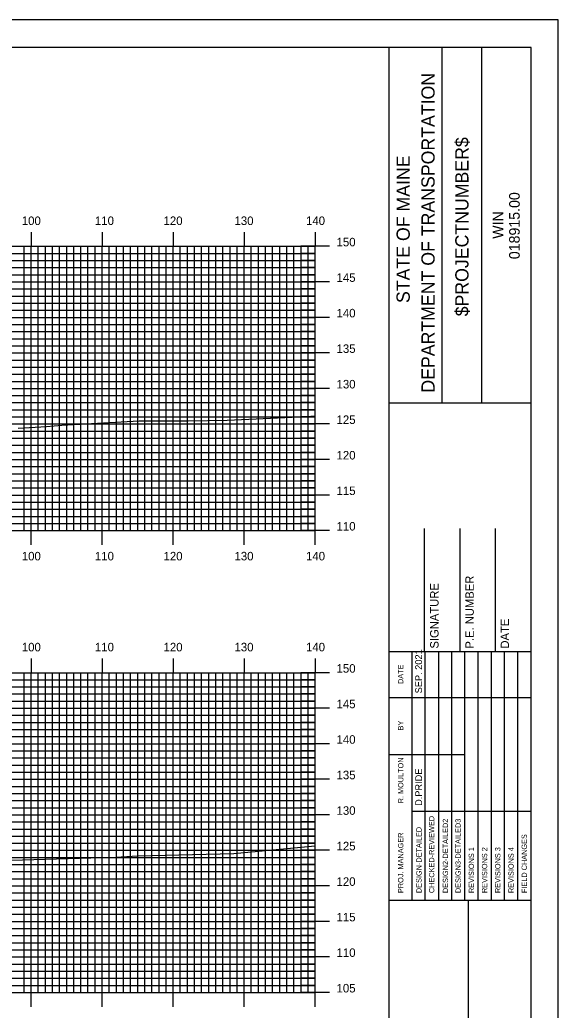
# Model space of a CAD drawing. Extents: x 1790124 to 1790467, y 442591 to 442811.
# Drawn here: x 1790388.1 to 1790463.9, y 442671.2 to 442810.5 of the extents above; entities that cross this region are included whole.
import ezdxf

# ---------------------------------------------------------------- set-up
doc = ezdxf.new("R2010")
doc.units = 0
for name, color, linetype in [('BORDER', 7, 'Continuous'), ('H_V ANNOTATION', 7, 'Continuous'), ('MAJOR', 7, 'Continuous'), ('MINOR', 7, 'Continuous'), ('PLOT BOUNDARY', 7, 'Continuous'), ('S_Roadway_Centerline', 7, 'Continuous')]:
    doc.layers.add(name, color=color, linetype=linetype)

msp = doc.modelspace()

# ---------------------------------------------------------------- linework, layer by layer
at = {"layer": 'BORDER'}
for p, q in [((1790440.1, 442596.67), (1790440.1, 442806.67)), ((1790447.55, 442756.66), (1790447.55, 442806.66)), ((1790453.14, 442756.66), (1790453.14, 442806.66)), ((1790440.1, 442756.65), (1790460.1, 442756.65)), ((1790445.1, 442721.67), (1790445.1, 442738.97)), ((1790450.1, 442721.67), (1790450.1, 442738.97)), ((1790455.1, 442721.67), (1790455.1, 442738.97)), ((1790440.1, 442721.67), (1790460.1, 442721.67)), ((1790440.1, 442686.67), (1790460.1, 442686.67)), ((1790451.28, 442616.67), (1790451.28, 442686.67))]:
    msp.add_line(p, q, dxfattribs=at)
msp.add_lwpolyline([(1790140.1, 442596.67), (1790460.1, 442596.67), (1790460.1, 442806.67), (1790140.1, 442806.67)], close=True, dxfattribs=at)
for points in [[(1790443.33, 442715.17), (1790443.33, 442721.67)], [(1790445.19, 442686.68), (1790445.19, 442721.67)], [(1790447.05, 442721.67), (1790447.05, 442686.68)], [(1790448.92, 442686.68), (1790448.92, 442721.67)], [(1790450.78, 442686.68), (1790450.78, 442721.67)], [(1790452.64, 442686.68), (1790452.64, 442721.67)], [(1790454.51, 442686.68), (1790454.51, 442721.67)], [(1790456.37, 442686.68), (1790456.37, 442721.67)], [(1790458.23, 442686.68), (1790458.23, 442721.67)], [(1790443.33, 442686.68), (1790443.33, 442720.26)], [(1790440.1, 442715.17), (1790460.1, 442715.17)], [(1790440.1, 442707.17), (1790443.33, 442707.17)], [(1790443.33, 442707.17), (1790450.78, 442707.17)], [(1790443.33, 442699.17), (1790460.1, 442699.17)]]:
    msp.add_lwpolyline(points, dxfattribs=at)
at = {"layer": 'MAJOR'}
for p, q in [((1790389.7, 442780.67), (1790389.7, 442778.67)), ((1790399.7, 442780.67), (1790399.7, 442778.67)), ((1790409.7, 442780.67), (1790409.7, 442778.67)), ((1790419.7, 442780.67), (1790419.7, 442778.67)), ((1790429.7, 442780.67), (1790429.7, 442778.67)), ((1790149.7, 442778.67), (1790429.7, 442778.67)), ((1790149.7, 442778.67), (1790429.7, 442778.67)), ((1790389.7, 442738.67), (1790389.7, 442778.67)), ((1790399.7, 442738.67), (1790399.7, 442778.67)), ((1790409.7, 442738.67), (1790409.7, 442778.67)), ((1790419.7, 442738.67), (1790419.7, 442778.67)), ((1790431.7, 442778.67), (1790427.69, 442778.67)), ((1790429.7, 442738.67), (1790429.7, 442778.67)), ((1790429.7, 442738.67), (1790429.7, 442778.67)), ((1790149.7, 442773.67), (1790429.7, 442773.67)), ((1790431.7, 442773.67), (1790427.69, 442773.67)), ((1790149.7, 442768.67), (1790429.7, 442768.67)), ((1790431.7, 442768.67), (1790427.69, 442768.67)), ((1790149.7, 442763.67), (1790429.7, 442763.67)), ((1790431.7, 442763.67), (1790427.69, 442763.67)), ((1790149.7, 442758.67), (1790429.7, 442758.67)), ((1790431.7, 442758.67), (1790427.69, 442758.67)), ((1790149.7, 442753.67), (1790429.7, 442753.67)), ((1790431.7, 442753.67), (1790427.69, 442753.67)), ((1790149.7, 442748.67), (1790429.7, 442748.67)), ((1790431.7, 442748.67), (1790427.69, 442748.67)), ((1790149.7, 442743.67), (1790429.7, 442743.67)), ((1790431.7, 442743.67), (1790427.69, 442743.67)), ((1790149.7, 442738.67), (1790429.7, 442738.67)), ((1790149.7, 442738.67), (1790429.7, 442738.67)), ((1790389.7, 442736.66), (1790389.7, 442738.67)), ((1790399.7, 442736.66), (1790399.7, 442738.67)), ((1790409.7, 442736.66), (1790409.7, 442738.67)), ((1790419.7, 442736.66), (1790419.7, 442738.67)), ((1790431.7, 442738.67), (1790427.69, 442738.67)), ((1790429.7, 442736.66), (1790429.7, 442738.67)), ((1790389.7, 442720.67), (1790389.7, 442718.67)), ((1790399.7, 442720.67), (1790399.7, 442718.67)), ((1790409.7, 442720.67), (1790409.7, 442718.67)), ((1790419.7, 442720.67), (1790419.7, 442718.67)), ((1790429.7, 442720.67), (1790429.7, 442718.67)), ((1790149.7, 442718.67), (1790429.7, 442718.67)), ((1790149.7, 442718.67), (1790429.7, 442718.67)), ((1790389.7, 442673.67), (1790389.7, 442718.67)), ((1790399.7, 442673.67), (1790399.7, 442718.67)), ((1790409.7, 442673.67), (1790409.7, 442718.67)), ((1790419.7, 442673.67), (1790419.7, 442718.67)), ((1790431.7, 442718.67), (1790427.69, 442718.67)), ((1790429.7, 442673.67), (1790429.7, 442718.67)), ((1790429.7, 442673.67), (1790429.7, 442718.67)), ((1790149.7, 442713.67), (1790429.7, 442713.67)), ((1790431.7, 442713.67), (1790427.69, 442713.67)), ((1790149.7, 442708.67), (1790429.7, 442708.67)), ((1790431.7, 442708.67), (1790427.69, 442708.67)), ((1790149.7, 442703.67), (1790429.7, 442703.67)), ((1790431.7, 442703.67), (1790427.69, 442703.67)), ((1790149.7, 442698.67), (1790429.7, 442698.67)), ((1790431.7, 442698.67), (1790427.69, 442698.67)), ((1790149.7, 442693.67), (1790429.7, 442693.67)), ((1790431.7, 442693.67), (1790427.69, 442693.67)), ((1790149.7, 442688.67), (1790429.7, 442688.67)), ((1790431.7, 442688.67), (1790427.69, 442688.67)), ((1790149.7, 442683.67), (1790429.7, 442683.67)), ((1790431.7, 442683.67), (1790427.69, 442683.67)), ((1790149.7, 442678.67), (1790429.7, 442678.67)), ((1790431.7, 442678.67), (1790427.69, 442678.67)), ((1790149.7, 442673.67), (1790429.7, 442673.67)), ((1790149.7, 442673.67), (1790429.7, 442673.67)), ((1790389.7, 442671.66), (1790389.7, 442673.67)), ((1790399.7, 442671.66), (1790399.7, 442673.67)), ((1790409.7, 442671.66), (1790409.7, 442673.67)), ((1790419.7, 442671.66), (1790419.7, 442673.67)), ((1790431.7, 442673.67), (1790427.69, 442673.67)), ((1790429.7, 442671.66), (1790429.7, 442673.67))]:
    msp.add_line(p, q, dxfattribs=at)
at = {"layer": 'MINOR'}
for p, q in [((1790388.7, 442738.67), (1790388.7, 442778.67)), ((1790390.7, 442738.67), (1790390.7, 442778.67)), ((1790391.7, 442738.67), (1790391.7, 442778.67)), ((1790392.7, 442738.67), (1790392.7, 442778.67)), ((1790393.7, 442738.67), (1790393.7, 442778.67)), ((1790394.7, 442738.67), (1790394.7, 442778.67)), ((1790395.7, 442738.67), (1790395.7, 442778.67)), ((1790396.7, 442738.67), (1790396.7, 442778.67)), ((1790397.7, 442738.67), (1790397.7, 442778.67)), ((1790398.7, 442738.67), (1790398.7, 442778.67)), ((1790400.7, 442738.67), (1790400.7, 442778.67)), ((1790401.7, 442738.67), (1790401.7, 442778.67)), ((1790402.7, 442738.67), (1790402.7, 442778.67)), ((1790403.7, 442738.67), (1790403.7, 442778.67)), ((1790404.7, 442738.67), (1790404.7, 442778.67)), ((1790405.7, 442738.67), (1790405.7, 442778.67)), ((1790406.7, 442738.67), (1790406.7, 442778.67)), ((1790407.7, 442738.67), (1790407.7, 442778.67)), ((1790408.7, 442738.67), (1790408.7, 442778.67)), ((1790410.7, 442738.67), (1790410.7, 442778.67)), ((1790411.7, 442738.67), (1790411.7, 442778.67)), ((1790412.7, 442738.67), (1790412.7, 442778.67)), ((1790413.7, 442738.67), (1790413.7, 442778.67)), ((1790414.7, 442738.67), (1790414.7, 442778.67)), ((1790415.7, 442738.67), (1790415.7, 442778.67)), ((1790416.7, 442738.67), (1790416.7, 442778.67)), ((1790417.7, 442738.67), (1790417.7, 442778.67)), ((1790418.7, 442738.67), (1790418.7, 442778.67)), ((1790420.7, 442738.67), (1790420.7, 442778.67)), ((1790421.7, 442738.67), (1790421.7, 442778.67)), ((1790422.7, 442738.67), (1790422.7, 442778.67)), ((1790423.7, 442738.67), (1790423.7, 442778.67)), ((1790424.7, 442738.67), (1790424.7, 442778.67)), ((1790425.7, 442738.67), (1790425.7, 442778.67)), ((1790426.7, 442738.67), (1790426.7, 442778.67)), ((1790427.7, 442738.67), (1790427.7, 442778.67)), ((1790428.7, 442738.67), (1790428.7, 442778.67)), ((1790149.7, 442777.67), (1790429.7, 442777.67)), ((1790429.7, 442777.67), (1790427.69, 442777.67)), ((1790149.7, 442776.67), (1790429.7, 442776.67)), ((1790149.7, 442775.67), (1790429.7, 442775.67)), ((1790429.7, 442776.67), (1790427.69, 442776.67)), ((1790429.7, 442775.67), (1790427.69, 442775.67)), ((1790149.7, 442774.67), (1790429.7, 442774.67)), ((1790429.7, 442774.67), (1790427.69, 442774.67)), ((1790149.7, 442772.67), (1790429.7, 442772.67)), ((1790149.7, 442771.67), (1790429.7, 442771.67)), ((1790429.7, 442772.67), (1790427.69, 442772.67)), ((1790429.7, 442771.67), (1790427.69, 442771.67)), ((1790149.7, 442770.67), (1790429.7, 442770.67)), ((1790429.7, 442770.67), (1790427.69, 442770.67)), ((1790149.7, 442769.67), (1790429.7, 442769.67)), ((1790429.7, 442769.67), (1790427.69, 442769.67)), ((1790149.7, 442767.67), (1790429.7, 442767.67)), ((1790429.7, 442767.67), (1790427.69, 442767.67)), ((1790149.7, 442766.67), (1790429.7, 442766.67)), ((1790429.7, 442766.67), (1790427.69, 442766.67)), ((1790149.7, 442765.67), (1790429.7, 442765.67)), ((1790149.7, 442764.67), (1790429.7, 442764.67)), ((1790429.7, 442765.67), (1790427.69, 442765.67)), ((1790429.7, 442764.67), (1790427.69, 442764.67)), ((1790149.7, 442762.67), (1790429.7, 442762.67)), ((1790149.7, 442761.67), (1790429.7, 442761.67)), ((1790429.7, 442762.67), (1790427.69, 442762.67)), ((1790429.7, 442761.67), (1790427.69, 442761.67)), ((1790149.7, 442760.67), (1790429.7, 442760.67)), ((1790429.7, 442760.67), (1790427.69, 442760.67)), ((1790149.7, 442759.67), (1790429.7, 442759.67)), ((1790429.7, 442759.67), (1790427.69, 442759.67)), ((1790149.7, 442757.67), (1790429.7, 442757.67)), ((1790429.7, 442757.67), (1790427.69, 442757.67)), ((1790149.7, 442756.67), (1790429.7, 442756.67)), ((1790429.7, 442756.67), (1790427.69, 442756.67)), ((1790149.7, 442755.67), (1790429.7, 442755.67)), ((1790149.7, 442754.67), (1790429.7, 442754.67)), ((1790429.7, 442755.67), (1790427.69, 442755.67)), ((1790429.7, 442754.67), (1790427.69, 442754.67)), ((1790149.7, 442752.67), (1790429.7, 442752.67)), ((1790429.7, 442752.67), (1790427.69, 442752.67)), ((1790149.7, 442751.67), (1790429.7, 442751.67)), ((1790149.7, 442750.67), (1790429.7, 442750.67)), ((1790429.7, 442751.67), (1790427.69, 442751.67)), ((1790429.7, 442750.67), (1790427.69, 442750.67)), ((1790149.7, 442749.67), (1790429.7, 442749.67)), ((1790429.7, 442749.67), (1790427.69, 442749.67)), ((1790149.7, 442747.67), (1790429.7, 442747.67)), ((1790429.7, 442747.67), (1790427.69, 442747.67)), ((1790149.7, 442746.67), (1790429.7, 442746.67)), ((1790429.7, 442746.67), (1790427.69, 442746.67)), ((1790149.7, 442745.67), (1790429.7, 442745.67)), ((1790429.7, 442745.67), (1790427.69, 442745.67)), ((1790149.7, 442744.67), (1790429.7, 442744.67)), ((1790429.7, 442744.67), (1790427.69, 442744.67)), ((1790149.7, 442742.67), (1790429.7, 442742.67)), ((1790429.7, 442742.67), (1790427.69, 442742.67)), ((1790149.7, 442741.67), (1790429.7, 442741.67)), ((1790429.7, 442741.67), (1790427.69, 442741.67)), ((1790149.7, 442740.67), (1790429.7, 442740.67)), ((1790149.7, 442739.67), (1790429.7, 442739.67)), ((1790429.7, 442740.67), (1790427.69, 442740.67)), ((1790429.7, 442739.67), (1790427.69, 442739.67)), ((1790388.7, 442673.67), (1790388.7, 442718.67)), ((1790390.7, 442673.67), (1790390.7, 442718.67)), ((1790391.7, 442673.67), (1790391.7, 442718.67)), ((1790392.7, 442673.67), (1790392.7, 442718.67)), ((1790393.7, 442673.67), (1790393.7, 442718.67)), ((1790394.7, 442673.67), (1790394.7, 442718.67)), ((1790395.7, 442673.67), (1790395.7, 442718.67)), ((1790396.7, 442673.67), (1790396.7, 442718.67)), ((1790397.7, 442673.67), (1790397.7, 442718.67)), ((1790398.7, 442673.67), (1790398.7, 442718.67)), ((1790400.7, 442673.67), (1790400.7, 442718.67)), ((1790401.7, 442673.67), (1790401.7, 442718.67)), ((1790402.7, 442673.67), (1790402.7, 442718.67)), ((1790403.7, 442673.67), (1790403.7, 442718.67)), ((1790404.7, 442673.67), (1790404.7, 442718.67)), ((1790405.7, 442673.67), (1790405.7, 442718.67)), ((1790406.7, 442673.67), (1790406.7, 442718.67)), ((1790407.7, 442673.67), (1790407.7, 442718.67)), ((1790408.7, 442673.67), (1790408.7, 442718.67)), ((1790410.7, 442673.67), (1790410.7, 442718.67)), ((1790411.7, 442673.67), (1790411.7, 442718.67)), ((1790412.7, 442673.67), (1790412.7, 442718.67)), ((1790413.7, 442673.67), (1790413.7, 442718.67)), ((1790414.7, 442673.67), (1790414.7, 442718.67)), ((1790415.7, 442673.67), (1790415.7, 442718.67)), ((1790416.7, 442673.67), (1790416.7, 442718.67)), ((1790417.7, 442673.67), (1790417.7, 442718.67)), ((1790418.7, 442673.67), (1790418.7, 442718.67)), ((1790420.7, 442673.67), (1790420.7, 442718.67)), ((1790421.7, 442673.67), (1790421.7, 442718.67)), ((1790422.7, 442673.67), (1790422.7, 442718.67)), ((1790423.7, 442673.67), (1790423.7, 442718.67)), ((1790424.7, 442673.67), (1790424.7, 442718.67)), ((1790425.7, 442673.67), (1790425.7, 442718.67)), ((1790426.7, 442673.67), (1790426.7, 442718.67)), ((1790427.7, 442673.67), (1790427.7, 442718.67)), ((1790428.7, 442673.67), (1790428.7, 442718.67)), ((1790149.7, 442717.67), (1790429.7, 442717.67)), ((1790429.7, 442717.67), (1790427.69, 442717.67)), ((1790149.7, 442716.67), (1790429.7, 442716.67)), ((1790149.7, 442715.67), (1790429.7, 442715.67)), ((1790429.7, 442716.67), (1790427.69, 442716.67)), ((1790429.7, 442715.67), (1790427.69, 442715.67)), ((1790149.7, 442714.67), (1790429.7, 442714.67)), ((1790429.7, 442714.67), (1790427.69, 442714.67)), ((1790149.7, 442712.67), (1790429.7, 442712.67)), ((1790149.7, 442711.67), (1790429.7, 442711.67)), ((1790429.7, 442712.67), (1790427.69, 442712.67)), ((1790429.7, 442711.67), (1790427.69, 442711.67)), ((1790149.7, 442710.67), (1790429.7, 442710.67)), ((1790429.7, 442710.67), (1790427.69, 442710.67)), ((1790149.7, 442709.67), (1790429.7, 442709.67)), ((1790429.7, 442709.67), (1790427.69, 442709.67)), ((1790149.7, 442707.67), (1790429.7, 442707.67)), ((1790429.7, 442707.67), (1790427.69, 442707.67)), ((1790149.7, 442706.67), (1790429.7, 442706.67)), ((1790429.7, 442706.67), (1790427.69, 442706.67)), ((1790149.7, 442705.67), (1790429.7, 442705.67)), ((1790149.7, 442704.67), (1790429.7, 442704.67)), ((1790429.7, 442705.67), (1790427.69, 442705.67)), ((1790429.7, 442704.67), (1790427.69, 442704.67)), ((1790149.7, 442702.67), (1790429.7, 442702.67)), ((1790149.7, 442701.67), (1790429.7, 442701.67)), ((1790429.7, 442702.67), (1790427.69, 442702.67)), ((1790429.7, 442701.67), (1790427.69, 442701.67)), ((1790149.7, 442700.67), (1790429.7, 442700.67)), ((1790429.7, 442700.67), (1790427.69, 442700.67)), ((1790149.7, 442699.67), (1790429.7, 442699.67)), ((1790429.7, 442699.67), (1790427.69, 442699.67)), ((1790149.7, 442697.67), (1790429.7, 442697.67)), ((1790429.7, 442697.67), (1790427.69, 442697.67)), ((1790149.7, 442696.67), (1790429.7, 442696.67)), ((1790429.7, 442696.67), (1790427.69, 442696.67)), ((1790149.7, 442695.67), (1790429.7, 442695.67)), ((1790429.7, 442695.67), (1790427.69, 442695.67)), ((1790149.7, 442694.67), (1790429.7, 442694.67)), ((1790429.7, 442694.67), (1790427.69, 442694.67)), ((1790149.7, 442692.67), (1790429.7, 442692.67)), ((1790429.7, 442692.67), (1790427.69, 442692.67)), ((1790149.7, 442691.67), (1790429.7, 442691.67)), ((1790149.7, 442690.67), (1790429.7, 442690.67)), ((1790429.7, 442691.67), (1790427.69, 442691.67)), ((1790429.7, 442690.67), (1790427.69, 442690.67)), ((1790149.7, 442689.67), (1790429.7, 442689.67)), ((1790429.7, 442689.67), (1790427.69, 442689.67)), ((1790149.7, 442687.67), (1790429.7, 442687.67)), ((1790149.7, 442686.67), (1790429.7, 442686.67)), ((1790429.7, 442687.67), (1790427.69, 442687.67)), ((1790429.7, 442686.67), (1790427.69, 442686.67)), ((1790149.7, 442685.67), (1790429.7, 442685.67)), ((1790429.7, 442685.67), (1790427.69, 442685.67)), ((1790149.7, 442684.67), (1790429.7, 442684.67)), ((1790429.7, 442684.67), (1790427.69, 442684.67)), ((1790149.7, 442682.67), (1790429.7, 442682.67)), ((1790429.7, 442682.67), (1790427.69, 442682.67)), ((1790149.7, 442681.67), (1790429.7, 442681.67)), ((1790429.7, 442681.67), (1790427.69, 442681.67)), ((1790149.7, 442680.67), (1790429.7, 442680.67)), ((1790149.7, 442679.67), (1790429.7, 442679.67)), ((1790429.7, 442680.67), (1790427.69, 442680.67)), ((1790429.7, 442679.67), (1790427.69, 442679.67)), ((1790149.7, 442677.67), (1790429.7, 442677.67)), ((1790149.7, 442676.67), (1790429.7, 442676.67)), ((1790429.7, 442677.67), (1790427.69, 442677.67)), ((1790429.7, 442676.67), (1790427.69, 442676.67)), ((1790149.7, 442675.67), (1790429.7, 442675.67)), ((1790429.7, 442675.67), (1790427.69, 442675.67)), ((1790149.7, 442674.67), (1790429.7, 442674.67)), ((1790429.7, 442674.67), (1790427.69, 442674.67))]:
    msp.add_line(p, q, dxfattribs=at)
at = {"layer": 'PLOT BOUNDARY'}
msp.add_lwpolyline([(1790123.91, 442590.55), (1790463.91, 442590.55), (1790463.91, 442810.55), (1790123.91, 442810.55)], close=True, dxfattribs=at)
at = {"layer": 'S_Roadway_Centerline'}
for points in [[(1790387.89, 442753.06), (1790391.85, 442753.33), (1790394.01, 442753.49), (1790404.92, 442754.13), (1790411.81, 442754.13), (1790417.31, 442754.22), (1790428.48, 442754.74), (1790429.7, 442754.81)], [(1790311.14, 442689.29), (1790316.74, 442690.36), (1790320.96, 442691.1), (1790322, 442691.1), (1790322.96, 442691.25), (1790323.85, 442691.32), (1790329.11, 442691.5), (1790331.43, 442691.36), (1790335.35, 442691.18), (1790344.98, 442691.22), (1790346.53, 442691.46), (1790347.03, 442691.47), (1790361.95, 442691.86), (1790363.08, 442691.88), (1790364.1, 442691.93), (1790375.22, 442692.11), (1790382, 442692.13), (1790398.11, 442692.63), (1790401.63, 442692.71), (1790404.68, 442692.9), (1790418.24, 442693.21), (1790429.7, 442694.28)]]:
    msp.add_lwpolyline(points, dxfattribs=at)

# ---------------------------------------------------------------- texts
at = {"layer": 'BORDER'}
for s, height, p in [('DEPARTMENT OF TRANSPORTATION', 1.8635, (1790446.51, 442758.08)), ('$PROJECTNUMBER$', 1.8635, (1790451.28, 442768.82)), ('STATE OF MAINE', 1.8635, (1790443.01, 442770.69)), ('018915.00', 1.491, (1790458.49, 442776.86)), ('WIN', 1.491, (1790456.17, 442779.73)), ('SIGNATURE', 1.181, (1790447.06, 442722.06)), ('P.E. NUMBER', 1.1811, (1790452.02, 442722.06)), ('DATE', 1.181, (1790456.98, 442722.06)), ('SEP. 2021', 0.969, (1790444.74, 442715.76)), ('DATE', 0.743, (1790442.1, 442717.08)), ('BY', 0.743, (1790442.1, 442710.54)), ('R. MOULTON', 0.745, (1790442.11, 442700.28)), ('D.PRIDE', 0.969, (1790444.74, 442699.92)), ('CHECKED-REVIEWED', 0.7455, (1790446.46, 442687.65)), ('DESIGN2-DETAILED2', 0.7455, (1790448.4, 442687.65)), ('DESIGN3-DETAILED3', 0.7455, (1790450.18, 442687.65)), ('DESIGN-DETAILED', 0.7455, (1790444.67, 442687.65)), ('PROJ. MANAGER', 0.7455, (1790442.1, 442687.65)), ('FIELD CHANGES', 0.7455, (1790459.5, 442687.65)), ('REVISIONS 1', 0.7455, (1790452.05, 442687.65)), ('REVISIONS 2', 0.7455, (1790453.91, 442687.65)), ('REVISIONS 3', 0.7455, (1790455.77, 442687.65)), ('REVISIONS 4', 0.7455, (1790457.64, 442687.65))]:
    msp.add_text(s, height=height, rotation=90, dxfattribs=at).set_placement(p)
at = {"layer": 'H_V ANNOTATION'}
for s, p in [('100', (1790388.38, 442781.67)), ('110', (1790398.68, 442781.67)), ('120', (1790408.34, 442781.67)), ('130', (1790418.33, 442781.67)), ('140', (1790428.4, 442781.67)), ('150', (1790432.7, 442778.67)), ('145', (1790432.7, 442773.67)), ('140', (1790432.7, 442768.67)), ('135', (1790432.7, 442763.67)), ('130', (1790432.7, 442758.67)), ('125', (1790432.7, 442753.67)), ('120', (1790432.7, 442748.67)), ('115', (1790432.7, 442743.67)), ('110', (1790432.7, 442738.67)), ('100', (1790388.38, 442734.47)), ('110', (1790398.68, 442734.47)), ('120', (1790408.34, 442734.47)), ('130', (1790418.33, 442734.47)), ('140', (1790428.4, 442734.47)), ('100', (1790388.38, 442721.67)), ('110', (1790398.68, 442721.67)), ('120', (1790408.34, 442721.67)), ('130', (1790418.33, 442721.67)), ('140', (1790428.4, 442721.67)), ('150', (1790432.7, 442718.67)), ('145', (1790432.7, 442713.67)), ('140', (1790432.7, 442708.67)), ('135', (1790432.7, 442703.67)), ('130', (1790432.7, 442698.67)), ('125', (1790432.7, 442693.67)), ('120', (1790432.7, 442688.67)), ('115', (1790432.7, 442683.67)), ('110', (1790432.7, 442678.67)), ('105', (1790432.7, 442673.67))]:
    msp.add_text(s, height=1.2, dxfattribs=at).set_placement(p)

doc.saveas('drawing.dxf')
